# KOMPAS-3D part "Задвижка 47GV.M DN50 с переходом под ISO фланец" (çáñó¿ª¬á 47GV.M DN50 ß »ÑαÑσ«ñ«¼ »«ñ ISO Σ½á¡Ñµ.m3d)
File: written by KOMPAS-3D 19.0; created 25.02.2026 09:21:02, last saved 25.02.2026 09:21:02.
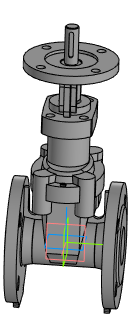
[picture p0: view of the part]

Document properties: Автор: Евгений; Полное имя файла: 47 GV.M DN50\Задвижка 47GV.M DN50 с маховиком.a3d

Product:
- Part/product: Задвижка 47GV.M DN50 с переходом под ISO фланец
    Масса: 13.8044
    Раздел спецификации: Документация
    Форматы листов документа: 2xA3
  - Component: Задвижка с обрезиненным клином DN50. Сборочный чертеж  | designation DR.47GVM.050.16.00.000СБ  | pos. 0  | Масса: 10.0548; Раздел спецификации: Документация; Форматы листов документа: 2xA3; source file: 47 GV.M DN50\DR.47GVM.050.16.00.000 СБ - Задвижка с обрезиненным клином DN100.cdw
- Part/product: Задвижка 47GV.M DN50 с переходом под ISO фланец  | designation 01
    Масса: 10.055
  - Component [detail]: Шпиндель  | pos. 5  | Материал: Сталь 20Х13 ГОСТ 5632-2014 (density 7670 kg/m3); Масса: 0.0837635; Раздел спецификации: Детали; source file: 47 GV.M DN50\DR.47GVM.050.16.00.003 - Шпиндель.cdw, 47 GV.M DN50\Шпиндель 47GV.M DN50.m3d
  - Component [detail]: Крышка  | pos. 4  | Материал: ВЧ50 ГОСТ 7293-85 (density 7200 kg/m3); Масса: 2.26467; Раздел спецификации: Детали; source file: 47 GV.M DN50\DR.47GVM.050.16.00.002 - Крышка.cdw, 47 GV.M DN50\Крышка 47GV.M DN50.m3d
  - Component [assembly]: Клин с направляющими  | designation DR.47GVM.050.16.01.000  | pos. 4  | Раздел спецификации: Сборочные единицы; Форматы листов документа: A4; source file: 47 GV.M DN50\DR.47GVM.050.16.01.000  - Клин с направляющими.a3d, 47 GV.M DN50\DR.47GVM.050.16.01.000  - Клин с направляющими.spw, 47 GV.M DN50\DR.47GVM.050.16.01.000  СБ - Клин с направляющими.cdw
  - Component [detail]: Корпус  | pos. 3  | Материал: ВЧ50 ГОСТ 7293-85 (density 7200 kg/m3); Масса: 6.814; Раздел спецификации: Детали; Форматы листов документа: 2xA3; source file: 47 GV.M DN50\DR.47GVM.050.16.00.001 - Корпус.cdw, 47 GV.M DN50\Корпус 47GV.M DN50.m3d
  - Component: Стойка  | Материал: ВЧ50 ГОСТ 7293-85 (density 7200 kg/m3); Масса: 1.73762; Раздел спецификации: Детали; Форматы листов документа: 2xA3; source file: 47 GV.M DN50\DR.47GVAM.050.16.00.001 - Стойка.cdw, 47 GV.M DN50\Стойка DN50.m3d
  - Component: Удлинитель шпинделя  | Материал: Сталь 20Х13 ГОСТ 5632-72 (density 7670 kg/m3); Масса: 0.268874; source file: 47 GV.M DN50\DR.47GVAM.050.16.00.002 - Удлинитель шпинделя.cdw, 47 GV.M DN50\Удлинитель шпинделя DN50.m3d

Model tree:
1. Операция без истории:1

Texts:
  Точка начала. Х
  Точка начала. Y
  Точка начала. Z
